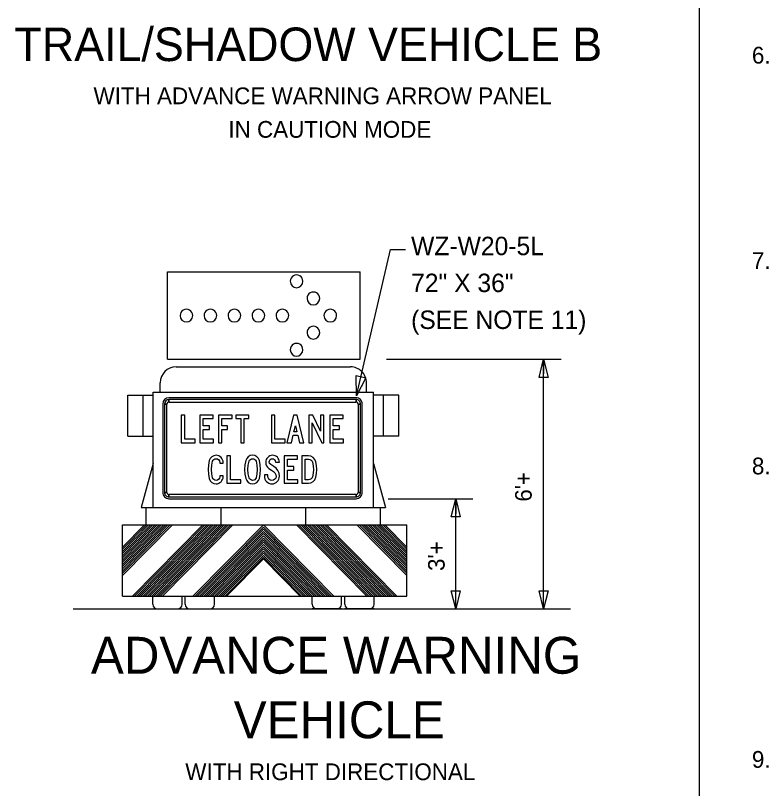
# Model space of a CAD drawing. Extents: x 1416408 to 1429341, y 372694 to 383211.
# Drawn here: x 1427689.2 to 1428140.7, y 373132.6 to 373595.9 of the extents above; entities that cross this region are included whole.
import ezdxf

# ---------------------------------------------------------------- set-up
doc = ezdxf.new("R2010")
doc.units = 0
doc.layers.add('Working Level 1', color=7, linetype='Continuous')

msp = doc.modelspace()

# ---------------------------------------------------------------- linework, layer by layer
at = {"layer": 'Working Level 1'}
for p, q in [((1428099.08, 374447.3), (1428099.08, 372727.17)), ((1427780.31, 373442.22), (1427895.86, 373442.22)), ((1427780.31, 373389.84), (1427780.31, 373442.22)), ((1427895.86, 373389.84), (1427895.86, 373442.22)), ((1427780.31, 373389.84), (1427895.86, 373389.84)), ((1427911.54, 373389.84), (1428016.33, 373389.84)), ((1428005.79, 373240.29), (1428005.79, 373389.84)), ((1428005.79, 373389.84), (1428005.79, 373381.07)), ((1427785.52, 373385.36), (1427890.09, 373385.36)), ((1427776.01, 373370.23), (1427776.01, 373375.75)), ((1427899.6, 373370.23), (1427899.6, 373375.75)), ((1427756.62, 373368.28), (1427771.7, 373368.28)), ((1427756.62, 373343.72), (1427756.62, 373368.28)), ((1427765.75, 373343.72), (1427765.75, 373368.28)), ((1427771.7, 373301.14), (1427771.7, 373370.23)), ((1427771.7, 373370.23), (1427903.91, 373370.23)), ((1427903.91, 373301.14), (1427903.91, 373370.23)), ((1427918.99, 373368.28), (1427903.91, 373368.28)), ((1427909.85, 373343.72), (1427909.85, 373368.28)), ((1427918.99, 373343.72), (1427918.99, 373368.28)), ((1427893.36, 373366.77), (1427781.21, 373366.77)), ((1427781.21, 373364.25), (1427781.21, 373365.72)), ((1427893.36, 373365.72), (1427893.36, 373364.25)), ((1427777.48, 373362.99), (1427777.48, 373310.08)), ((1427778.51, 373362.99), (1427779.97, 373362.99)), ((1427894.6, 373362.99), (1427896.06, 373362.99)), ((1427897.1, 373310.08), (1427897.1, 373362.99)), ((1427756.62, 373343.72), (1427771.7, 373343.72)), ((1427918.99, 373343.72), (1427903.91, 373343.72)), ((1427771.7, 373327.46), (1427764.55, 373301.14)), ((1427903.91, 373327.46), (1427911.06, 373301.14)), ((1427779.97, 373310.08), (1427778.51, 373310.08)), ((1427781.21, 373307.35), (1427781.21, 373308.82)), ((1427893.36, 373308.82), (1427893.36, 373307.35)), ((1427896.06, 373310.08), (1427894.6, 373310.08)), ((1427781.21, 373306.3), (1427893.36, 373306.3)), ((1427912.62, 373306.3), (1427963.33, 373306.3)), ((1427953.11, 373240.29), (1427953.11, 373306.3)), ((1427953.11, 373306.3), (1427953.11, 373297.38)), ((1427764.55, 373301.14), (1427911.06, 373301.14)), ((1427767.52, 373290.58), (1427767.52, 373301.14)), ((1427812.44, 373290.58), (1427812.44, 373300.94)), ((1427863.17, 373290.58), (1427863.17, 373300.94)), ((1427908.09, 373290.58), (1427908.09, 373301.14)), ((1427753.33, 373290.58), (1427923.83, 373290.58)), ((1427753.33, 373290.58), (1427923.83, 373290.58)), ((1427753.33, 373290.58), (1427923.83, 373290.58)), ((1427753.33, 373290.58), (1427923.83, 373290.58)), ((1427753.33, 373247.89), (1427753.33, 373290.58)), ((1427753.33, 373277.22), (1427766.55, 373290.58)), ((1427753.33, 373261.68), (1427781.91, 373290.58)), ((1427753.33, 373262.99), (1427780.62, 373290.58)), ((1427753.33, 373264.3), (1427779.33, 373290.58)), ((1427753.33, 373265.59), (1427778.05, 373290.58)), ((1427753.33, 373266.9), (1427776.76, 373290.58)), ((1427753.33, 373268.2), (1427775.46, 373290.58)), ((1427753.33, 373269.49), (1427774.19, 373290.58)), ((1427753.33, 373270.8), (1427772.9, 373290.58)), ((1427753.33, 373272.11), (1427771.6, 373290.58)), ((1427753.33, 373273.42), (1427770.31, 373290.58)), ((1427753.33, 373274.71), (1427769.03, 373290.58)), ((1427753.33, 373276.01), (1427767.74, 373290.58)), ((1427753.33, 373260.39), (1427783.16, 373290.55)), ((1427759.28, 373247.89), (1427801.51, 373290.58)), ((1427760.56, 373247.89), (1427802.79, 373290.58)), ((1427761.86, 373247.89), (1427804.08, 373290.58)), ((1427763.15, 373247.89), (1427805.38, 373290.58)), ((1427764.42, 373247.89), (1427806.65, 373290.58)), ((1427765.72, 373247.89), (1427807.95, 373290.58)), ((1427767.01, 373247.89), (1427809.24, 373290.58)), ((1427768.3, 373247.89), (1427810.53, 373290.58)), ((1427769.58, 373247.89), (1427811.81, 373290.58)), ((1427770.87, 373247.89), (1427813.1, 373290.58)), ((1427772.17, 373247.89), (1427814.39, 373290.58)), ((1427773.44, 373247.89), (1427815.67, 373290.58)), ((1427774.74, 373247.89), (1427816.96, 373290.58)), ((1427776.03, 373247.89), (1427818.24, 373290.57)), ((1427777.31, 373247.89), (1427819.54, 373290.58)), ((1427795.58, 373247.89), (1427837.8, 373290.58)), ((1427796.86, 373247.89), (1427837.8, 373289.28)), ((1427880.03, 373247.89), (1427837.8, 373290.58)), ((1427878.68, 373247.96), (1427837.8, 373289.28)), ((1427899.84, 373247.89), (1427857.62, 373290.58)), ((1427901.13, 373247.89), (1427858.92, 373290.57)), ((1427902.42, 373247.89), (1427860.19, 373290.58)), ((1427903.72, 373247.89), (1427861.49, 373290.58)), ((1427904.99, 373247.89), (1427862.76, 373290.58)), ((1427906.28, 373247.89), (1427864.06, 373290.58)), ((1427907.58, 373247.89), (1427865.35, 373290.58)), ((1427908.85, 373247.89), (1427866.62, 373290.58)), ((1427910.15, 373247.89), (1427867.92, 373290.58)), ((1427911.44, 373247.89), (1427869.21, 373290.58)), ((1427912.73, 373247.89), (1427870.5, 373290.58)), ((1427914.01, 373247.89), (1427871.78, 373290.58)), ((1427915.3, 373247.89), (1427873.07, 373290.58)), ((1427916.6, 373247.89), (1427874.37, 373290.58)), ((1427917.88, 373247.89), (1427875.65, 373290.58)), ((1427923.83, 373260.39), (1427894, 373290.55)), ((1427923.83, 373261.68), (1427895.24, 373290.58)), ((1427923.83, 373262.99), (1427896.54, 373290.58)), ((1427923.83, 373264.3), (1427897.83, 373290.58)), ((1427923.83, 373265.59), (1427899.11, 373290.58)), ((1427923.83, 373266.9), (1427900.4, 373290.58)), ((1427923.83, 373268.2), (1427901.69, 373290.58)), ((1427923.83, 373269.49), (1427902.97, 373290.58)), ((1427923.83, 373270.8), (1427904.26, 373290.58)), ((1427923.83, 373272.11), (1427905.56, 373290.58)), ((1427923.83, 373273.42), (1427906.85, 373290.58)), ((1427923.83, 373274.71), (1427908.12, 373290.58)), ((1427923.83, 373276.01), (1427909.42, 373290.58)), ((1427923.83, 373277.22), (1427910.61, 373290.58)), ((1427923.83, 373247.89), (1427923.83, 373290.58)), ((1427798.15, 373247.89), (1427837.8, 373287.98)), ((1427799.45, 373247.89), (1427837.8, 373286.67)), ((1427800.72, 373247.89), (1427837.8, 373285.38)), ((1427877.46, 373247.89), (1427837.8, 373287.98)), ((1427876.17, 373247.89), (1427837.8, 373286.67)), ((1427874.9, 373247.89), (1427837.8, 373285.38)), ((1427802.02, 373247.89), (1427837.8, 373284.07)), ((1427803.31, 373247.89), (1427837.8, 373282.76)), ((1427804.58, 373247.89), (1427837.8, 373281.48)), ((1427805.88, 373247.89), (1427837.8, 373280.17)), ((1427873.6, 373247.89), (1427837.8, 373284.07)), ((1427872.31, 373247.89), (1427837.8, 373282.76)), ((1427871.03, 373247.89), (1427837.8, 373281.48)), ((1427869.74, 373247.89), (1427837.8, 373280.17)), ((1427807.17, 373247.89), (1427837.8, 373278.86)), ((1427808.46, 373247.89), (1427837.8, 373277.55)), ((1427809.74, 373247.89), (1427837.8, 373276.26)), ((1427868.45, 373247.89), (1427837.8, 373278.86)), ((1427867.15, 373247.89), (1427837.8, 373277.55)), ((1427865.88, 373247.89), (1427837.8, 373276.26)), ((1427811.03, 373247.89), (1427837.8, 373274.96)), ((1427812.33, 373247.89), (1427837.8, 373273.65)), ((1427813.6, 373247.89), (1427837.8, 373272.36)), ((1427814.89, 373247.89), (1427837.8, 373271.06)), ((1427864.58, 373247.89), (1427837.8, 373274.96)), ((1427863.29, 373247.89), (1427837.8, 373273.65)), ((1427862.02, 373247.89), (1427837.8, 373272.36)), ((1427860.72, 373247.89), (1427837.8, 373271.06)), ((1427815.97, 373248.14), (1427837.8, 373270.21)), ((1427859.88, 373247.89), (1427837.8, 373270.21)), ((1427753.33, 373247.89), (1427923.83, 373247.89)), ((1427753.33, 373247.89), (1427923.83, 373247.89)), ((1427753.33, 373247.89), (1427923.83, 373247.89)), ((1427753.33, 373247.89), (1427923.83, 373247.89)), ((1427771.45, 373243.05), (1427771.45, 373247.89)), ((1427789.06, 373243.05), (1427789.06, 373247.89)), ((1427790.88, 373243.05), (1427790.88, 373247.89)), ((1427808.5, 373243.05), (1427808.5, 373247.89)), ((1427867.11, 373243.05), (1427867.11, 373247.89)), ((1427884.72, 373243.05), (1427884.72, 373247.89)), ((1427886.55, 373243.05), (1427886.55, 373247.89)), ((1427904.16, 373243.05), (1427904.16, 373247.89)), ((1427723.72, 373240.29), (1428022.01, 373240.29)), ((1427771.45, 373240.29), (1427789.06, 373240.29)), ((1427771.45, 373240.29), (1427789.06, 373240.29)), ((1427771.45, 373240.29), (1427789.06, 373240.29)), ((1427771.45, 373240.29), (1427789.06, 373240.29)), ((1427790.88, 373240.29), (1427808.5, 373240.29)), ((1427790.88, 373240.29), (1427808.5, 373240.29)), ((1427790.88, 373240.29), (1427808.5, 373240.29)), ((1427790.88, 373240.29), (1427808.5, 373240.29)), ((1427884.72, 373240.29), (1427867.11, 373240.29)), ((1427884.72, 373240.29), (1427867.11, 373240.29)), ((1427884.72, 373240.29), (1427867.11, 373240.29)), ((1427884.72, 373240.29), (1427867.11, 373240.29)), ((1427904.16, 373240.29), (1427886.55, 373240.29)), ((1427904.16, 373240.29), (1427886.55, 373240.29)), ((1427904.16, 373240.29), (1427886.55, 373240.29)), ((1427904.16, 373240.29), (1427886.55, 373240.29))]:
    msp.add_line(p, q, dxfattribs=at)
for points in [[(1427893.6, 373367.86), (1427914.05, 373455.6), (1427922.99, 373455.6)], [(1427862.15, 373339.89), (1427858.17, 373356.39), (1427855.86, 373356.39), (1427851.88, 373339.89), (1427854.58, 373339.89), (1427855.64, 373344.31), (1427858.38, 373344.31), (1427859.45, 373339.89), (1427862.15, 373339.89)], [(1427857.89, 373346.37), (1427856.14, 373346.37), (1427857.02, 373350), (1427857.89, 373346.37)], [(1427836.16, 373323.79), (1427835.97, 373326.57), (1427835.43, 373329.25), (1427834.87, 373330.48), (1427833.93, 373331.47), (1427832.72, 373332.12), (1427831.35, 373332.33), (1427829.98, 373332.11), (1427828.77, 373331.46), (1427827.83, 373330.47), (1427827.26, 373329.23), (1427826.72, 373326.54), (1427826.54, 373323.79), (1427826.72, 373321.06), (1427827.26, 373318.37), (1427827.82, 373317.13), (1427828.76, 373316.12), (1427829.98, 373315.46), (1427831.35, 373315.24), (1427832.73, 373315.46), (1427833.95, 373316.12), (1427834.88, 373317.13), (1427835.45, 373318.39), (1427835.98, 373321.07), (1427836.16, 373323.79)], [(1427860.83, 373315.54), (1427864.81, 373315.54), (1427866.34, 373315.79), (1427867.7, 373316.55), (1427868.74, 373317.69), (1427869.33, 373319.12), (1427869.73, 373321.42), (1427869.86, 373323.79), (1427869.73, 373326.15), (1427869.33, 373328.46), (1427868.74, 373329.87), (1427867.7, 373331.02), (1427866.34, 373331.78), (1427864.81, 373332.04), (1427860.83, 373332.04), (1427860.83, 373315.54)], [(1427834.12, 373323.79), (1427833.94, 373321.24), (1427833.41, 373318.75), (1427833.12, 373318.17), (1427832.65, 373317.71), (1427832.04, 373317.4), (1427831.35, 373317.3), (1427830.66, 373317.4), (1427830.05, 373317.72), (1427829.57, 373318.19), (1427829.29, 373318.77), (1427828.76, 373321.26), (1427828.58, 373323.79), (1427828.76, 373326.33), (1427829.29, 373328.82), (1427829.57, 373329.4), (1427830.05, 373329.86), (1427830.66, 373330.17), (1427831.35, 373330.27), (1427832.04, 373330.17), (1427832.65, 373329.86), (1427833.12, 373329.4), (1427833.41, 373328.83), (1427833.94, 373326.35), (1427834.12, 373323.79)], [(1427862.87, 373317.6), (1427862.87, 373329.97), (1427864.86, 373329.97), (1427865.69, 373329.84), (1427866.43, 373329.45), (1427867, 373328.85), (1427867.32, 373328.11), (1427867.69, 373325.97), (1427867.82, 373323.79), (1427867.69, 373321.59), (1427867.32, 373319.46), (1427867, 373318.72), (1427866.43, 373318.12), (1427865.69, 373317.73), (1427864.86, 373317.6), (1427862.87, 373317.6)]]:
    msp.add_lwpolyline(points, dxfattribs=at)
for points in [[(1428003.1, 373378.96), (1428005.79, 373389.84), (1428008.48, 373378.96)], [(1427899.2, 373378.83), (1427893.6, 373367.86), (1427893.44, 373380.2)], [(1427893.36, 373365.72), (1427781.21, 373365.72), (1427781.21, 373364.25), (1427893.36, 373364.25), (1427893.36, 373365.72)], [(1427778.51, 373362.99), (1427778.51, 373310.08), (1427779.97, 373310.08), (1427779.97, 373362.99), (1427778.51, 373362.99)], [(1427896.06, 373310.08), (1427896.06, 373362.99), (1427894.6, 373362.99), (1427894.6, 373310.08), (1427896.06, 373310.08)], [(1427796.84, 373339.89), (1427796.84, 373341.95), (1427790.66, 373341.95), (1427790.66, 373356.39), (1427788.62, 373356.39), (1427788.62, 373339.89)], [(1427807.95, 373339.89), (1427807.95, 373341.95), (1427801.77, 373341.95), (1427801.77, 373347.85), (1427805.56, 373347.85), (1427805.56, 373349.91), (1427801.77, 373349.91), (1427801.77, 373354.33), (1427807.69, 373354.33), (1427807.69, 373356.39), (1427799.73, 373356.39), (1427799.73, 373339.89)], [(1427819.07, 373354.33), (1427819.07, 373356.39), (1427810.84, 373356.39), (1427810.84, 373339.89), (1427812.88, 373339.89), (1427812.88, 373347.85), (1427816.38, 373347.85), (1427816.38, 373349.91), (1427812.88, 373349.91), (1427812.88, 373354.33)], [(1427829.19, 373354.33), (1427829.19, 373356.39), (1427821.32, 373356.39), (1427821.32, 373354.33), (1427824.24, 373354.33), (1427824.24, 373339.89), (1427826.28, 373339.89), (1427826.28, 373354.33)], [(1427850.85, 373339.89), (1427850.85, 373341.95), (1427844.67, 373341.95), (1427844.67, 373356.39), (1427842.63, 373356.39), (1427842.63, 373339.89)], [(1427874.1, 373339.89), (1427874.1, 373356.39), (1427872.06, 373356.39), (1427872.06, 373346.77), (1427867.43, 373356.39), (1427865.07, 373356.39), (1427865.07, 373339.89), (1427867.11, 373339.89), (1427867.11, 373351.69), (1427872.78, 373339.89)], [(1427885.87, 373339.89), (1427885.87, 373341.95), (1427879.69, 373341.95), (1427879.69, 373347.85), (1427883.48, 373347.85), (1427883.48, 373349.91), (1427879.69, 373349.91), (1427879.69, 373354.33), (1427885.61, 373354.33), (1427885.61, 373356.39), (1427877.65, 373356.39), (1427877.65, 373339.89)], [(1427813.7, 373319.95), (1427811.66, 373319.95), (1427811.66, 373319.48), (1427811.5, 373318.65), (1427811.02, 373317.94), (1427810.32, 373317.46), (1427809.49, 373317.3), (1427808.8, 373317.4), (1427808.18, 373317.72), (1427807.69, 373318.19), (1427807.41, 373318.77), (1427806.88, 373321.24), (1427806.7, 373323.79), (1427806.88, 373326.31), (1427807.41, 373328.78), (1427807.69, 373329.38), (1427808.18, 373329.85), (1427808.8, 373330.16), (1427809.49, 373330.27), (1427810.32, 373330.11), (1427811.02, 373329.63), (1427811.5, 373328.92), (1427811.66, 373328.09), (1427811.66, 373327.62), (1427813.7, 373327.62), (1427813.7, 373328.03), (1427813.62, 373328.89), (1427813.39, 373329.68), (1427813, 373330.4), (1427812.46, 373331.07), (1427811.8, 373331.62), (1427811.09, 373332.01), (1427810.3, 373332.25), (1427809.45, 373332.33), (1427808.08, 373332.1), (1427806.86, 373331.44), (1427805.92, 373330.43), (1427805.35, 373329.18), (1427804.83, 373326.5), (1427804.66, 373323.79), (1427804.84, 373321.04), (1427805.37, 373318.37), (1427805.93, 373317.12), (1427806.88, 373316.12), (1427808.08, 373315.46), (1427809.45, 373315.24), (1427810.3, 373315.32), (1427811.09, 373315.55), (1427811.8, 373315.94), (1427812.46, 373316.5), (1427813, 373317.16), (1427813.39, 373317.89), (1427813.62, 373318.67), (1427813.7, 373319.54)], [(1427824.21, 373315.54), (1427824.21, 373317.6), (1427818.03, 373317.6), (1427818.03, 373332.04), (1427815.99, 373332.04), (1427815.99, 373315.54)], [(1427838.39, 373320.54), (1427838.39, 373319.87), (1427838.47, 373318.94), (1427838.72, 373318.09), (1427839.13, 373317.3), (1427839.71, 373316.59), (1427840.4, 373316), (1427841.17, 373315.58), (1427842, 373315.32), (1427842.9, 373315.24), (1427843.81, 373315.32), (1427844.64, 373315.57), (1427845.41, 373315.99), (1427846.11, 373316.58), (1427846.68, 373317.28), (1427847.09, 373318.06), (1427847.34, 373318.9), (1427847.43, 373319.81), (1427847.19, 373321.56), (1427846.51, 373323.19), (1427845.47, 373324.56), (1427844.11, 373325.63), (1427842.34, 373326.75), (1427841.56, 373327.43), (1427841.31, 373328.38), (1427841.44, 373329.1), (1427841.85, 373329.71), (1427842.45, 373330.13), (1427843.16, 373330.27), (1427843.87, 373330.12), (1427844.48, 373329.66), (1427844.89, 373328.99), (1427845.02, 373328.21), (1427847.43, 373328.21), (1427847.35, 373329.03), (1427847.13, 373329.79), (1427846.75, 373330.48), (1427846.22, 373331.12), (1427845.59, 373331.65), (1427844.9, 373332.03), (1427844.15, 373332.25), (1427843.35, 373332.33), (1427842.52, 373332.25), (1427841.77, 373332.02), (1427841.08, 373331.63), (1427840.45, 373331.09), (1427839.93, 373330.43), (1427839.56, 373329.72), (1427839.34, 373328.93), (1427839.27, 373328.09), (1427839.37, 373326.95), (1427839.7, 373325.96), (1427840.23, 373325.12), (1427841, 373324.43), (1427842.78, 373323.34), (1427843.92, 373322.61), (1427844.74, 373321.74), (1427845.22, 373320.7), (1427845.39, 373319.53), (1427845.2, 373318.67), (1427844.66, 373317.95), (1427843.85, 373317.46), (1427842.9, 373317.3), (1427841.95, 373317.48), (1427841.15, 373318.04), (1427840.61, 373318.85), (1427840.43, 373319.81), (1427840.43, 373320.54)], [(1427858.5, 373315.54), (1427858.5, 373317.6), (1427852.32, 373317.6), (1427852.32, 373323.49), (1427856.1, 373323.49), (1427856.1, 373325.55), (1427852.32, 373325.55), (1427852.32, 373329.97), (1427858.24, 373329.97), (1427858.24, 373332.04), (1427850.28, 373332.04), (1427850.28, 373315.54)], [(1427781.21, 373307.35), (1427893.36, 373307.35), (1427893.36, 373308.82), (1427781.21, 373308.82), (1427781.21, 373307.35)], [(1427950.41, 373295.41), (1427953.11, 373306.3), (1427955.8, 373295.41)], [(1427955.8, 373251.18), (1427953.11, 373240.29), (1427950.41, 373251.18)], [(1428008.48, 373251.18), (1428005.79, 373240.29), (1428003.1, 373251.18)]]:
    msp.add_lwpolyline(points, close=True, dxfattribs=at)
for centre, major_axis, start_param, end_param in [((1427857.68, 373436.57), (0, 3.84), 4.712389, 7.853982), ((1427857.68, 373436.57), (0, 3.84), 1.570797, 4.712389), ((1427867.82, 373426.3), (0, 3.84), 4.712389, 7.853982), ((1427867.82, 373426.3), (0, 3.84), 1.570797, 4.712389), ((1427791.71, 373416.04), (0, 3.84), 4.712389, 7.853982), ((1427806.08, 373416.04), (0, 3.84), 4.712389, 7.853982), ((1427820.46, 373416.04), (0, 3.84), 4.712389, 7.853982), ((1427834.83, 373416.04), (0, 3.84), 4.712389, 7.853982), ((1427849.2, 373416.04), (0, 3.84), 4.712389, 7.853982), ((1427877.95, 373416.04), (0, 3.84), 4.712389, 7.853982), ((1427791.71, 373416.04), (0, 3.84), 1.570797, 4.712389), ((1427806.08, 373416.04), (0, 3.84), 1.570797, 4.712389), ((1427820.46, 373416.04), (0, 3.84), 1.570797, 4.712389), ((1427834.83, 373416.04), (0, 3.84), 1.570797, 4.712389), ((1427849.2, 373416.04), (0, 3.84), 1.570797, 4.712389), ((1427877.95, 373416.04), (0, 3.84), 1.570797, 4.712389), ((1427867.82, 373405.79), (0, 3.84), 4.712389, 7.853982), ((1427867.82, 373405.79), (0, 3.84), 1.570797, 4.712389), ((1427857.68, 373395.54), (0, 3.84), 4.712389, 7.853982), ((1427857.68, 373395.54), (0, 3.84), 1.570797, 4.712389), ((1427785.52, 373375.75), (0, 9.61), 6.283185, 7.853981), ((1427890.09, 373375.75), (0, 9.61), 4.712389, 6.283186), ((1427781.21, 373362.99), (0, 3.78), 0.000004, 1.570794), ((1427781.21, 373362.99), (0, 2.73), 0.000004, 1.570794), ((1427781.21, 373362.99), (0, 1.26), 0.000004, 1.570794), ((1427893.36, 373362.99), (0, 3.78), 4.712389, 6.283189), ((1427893.36, 373362.99), (0, 2.73), 4.712389, 6.283189), ((1427893.36, 373362.99), (0, 1.26), 4.712389, 6.283189), ((1427781.21, 373310.08), (0, 3.78), 1.570794, 3.141594), ((1427781.21, 373310.08), (0, 2.73), 1.570794, 3.141594), ((1427781.21, 373310.08), (0, 1.26), 1.570794, 3.141594), ((1427893.36, 373310.08), (0, 3.78), 3.141594, 4.712394), ((1427893.36, 373310.08), (0, 2.73), 3.141594, 4.712394), ((1427893.36, 373310.08), (0, 1.26), 3.141594, 4.712394), ((1427774.18, 373243.05), (0, -2.76), 4.712389, 6.283185), ((1427786.33, 373243.05), (0, 2.76), 3.141593, 4.712389), ((1427793.62, 373243.05), (0, -2.76), 4.712389, 6.283185), ((1427805.77, 373243.05), (0, 2.76), 3.141593, 4.712389), ((1427869.84, 373243.05), (0, -2.76), 4.712389, 6.283185), ((1427881.99, 373243.05), (0, 2.76), 3.141593, 4.712389), ((1427889.28, 373243.05), (0, -2.76), 4.712389, 6.283185), ((1427901.43, 373243.05), (0, 2.76), 3.141593, 4.712389)]:
    msp.add_ellipse(centre, major_axis=major_axis, ratio=0.989089, start_param=start_param, end_param=end_param, dxfattribs=at)

# ---------------------------------------------------------------- texts
for s, height, p in [('TRAIL/SHADOW VEHICLE B', 20.0929, (1427688.58, 373568.54)), ('6. ', 10.046, (1428130.69, 373567.03)), ('WITH ADVANCE WARNING ARROW PANEL', 10.0465, (1427735.99, 373542.69)), ('IN CAUTION MODE', 10.0465, (1427816.82, 373522.59)), ('WZ-W20-5L', 11.051, (1427926.37, 373452.23)), ('7. ', 10.046, (1428130.69, 373443.96)), ('72" X 36"', 11.051, (1427926.37, 373430.12)), ('(SEE NOTE 11)', 11.0511, (1427926.37, 373408.02)), ('8.', 10.046, (1428130.69, 373320.89)), ('ADVANCE WARNING', 22.1022, (1427734.42, 373201.45)), ('VEHICLE ', 22.102, (1427820.06, 373162.77)), ('9.', 10.046, (1428130.69, 373145.08)), ('WITH RIGHT DIRECTIONAL', 10.0465, (1427791, 373137.66))]:
    msp.add_text(s, height=height, dxfattribs=at).set_placement(p)
for s, p in [("6'+", (1427998.67, 373304.58)), ("3'+", (1427946.5, 373263.05))]:
    msp.add_text(s, height=9.937, rotation=90, dxfattribs=at).set_placement(p)

doc.saveas('drawing.dxf')
